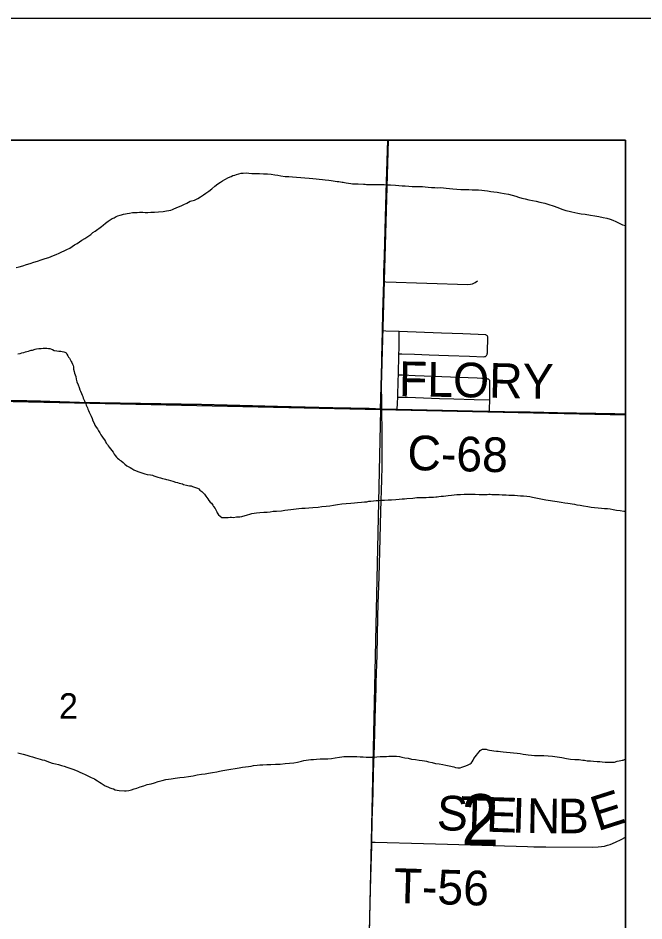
# Model space of a CAD drawing. Extents: x 2.4 to 73.1, y 4.5 to 25.6.
# Drawn here: x 35.8 to 36.312, y 24.146 to 24.885 of the extents above; entities that cross this region are included whole.
import ezdxf

# ---------------------------------------------------------------- set-up
doc = ezdxf.new("R2010")
doc.units = 0
for name, color, linetype in [('GM_X_County_Road', 7, 'Continuous'), ('GM_X_County_Road_Text', 7, 'Continuous'), ('GM_X_Interchange_Ramps', 7, 'Continuous'), ('GM_X_Minor_River', 7, 'Continuous'), ('GM_X_Section', 7, 'Continuous'), ('GM_X_Section_Text', 7, 'Continuous'), ('GM_X_State_Route', 7, 'Continuous'), ('GM_X_Township_Road', 7, 'Continuous'), ('GM_X_Township_Road_Text', 7, 'Continuous'), ('GM_X_US_Shield', 7, 'Continuous'), ('SH_Cut_Line', 7, 'Continuous'), ('SH_Data', 7, 'Continuous')]:
    doc.layers.add(name, color=color, linetype=linetype)

msp = doc.modelspace()

# ---------------------------------------------------------------- linework, layer by layer
at = {"layer": 'GM_X_County_Road'}
for points in [[(36.09775, 24.56499), (36.10949, 24.56462), (36.11043, 24.5646)], [(36.11043, 24.5646), (36.15984, 24.5635), (36.18439, 24.563), (36.18603, 24.56297), (36.2108, 24.56249), (36.2195, 24.56235), (36.24188, 24.56193), (36.28881, 24.56101), (36.29738, 24.56082)]]:
    msp.add_lwpolyline(points, dxfattribs=at)
at = {"layer": 'GM_X_Interchange_Ramps'}
msp.add_lwpolyline([(35.79125, 24.57227), (35.80687, 24.57187), (35.81806, 24.57163), (35.82569, 24.57146), (35.8339, 24.57128), (35.85005, 24.57076), (35.86657, 24.57026), (35.90005, 24.56968), (35.9501, 24.56885), (35.98148, 24.56812), (36.01225, 24.56734), (36.03494, 24.56679), (36.05754, 24.56627), (36.08746, 24.56558), (36.09258, 24.56544), (36.09763, 24.56527), (36.10937, 24.5649), (36.11031, 24.56487), (36.15972, 24.56377), (36.18427, 24.56327), (36.18592, 24.56324), (36.21068, 24.56276), (36.21939, 24.56263), (36.24176, 24.56221), (36.28869, 24.56128), (36.29738, 24.56109), (36.29738, 24.78522), (33.56842, 24.78522)], dxfattribs=at)
at = {"layer": 'GM_X_Minor_River'}
for points in [[(35.97726, 24.7565), (35.9788, 24.75721), (35.98071, 24.75773), (35.98243, 24.75806), (35.98414, 24.7582), (35.9868, 24.75832), (35.9887, 24.75826), (35.99135, 24.75799), (35.99439, 24.75791), (35.99743, 24.75782), (36.00084, 24.75772), (36.00407, 24.75763), (36.0071, 24.75735), (36.01012, 24.75688), (36.01258, 24.75643), (36.01485, 24.75599), (36.01844, 24.7555), (36.02148, 24.75542), (36.02451, 24.75514), (36.02792, 24.75485), (36.03133, 24.75475), (36.03474, 24.75446), (36.03815, 24.75418), (36.04118, 24.7539), (36.04384, 24.75363), (36.04649, 24.75337), (36.04913, 24.75291), (36.0514, 24.75265), (36.05425, 24.75238), (36.05614, 24.75214), (36.05784, 24.7519), (36.05954, 24.75166), (36.06125, 24.75142), (36.06257, 24.75138), (36.06389, 24.75097), (36.06521, 24.75074), (36.06616, 24.75071), (36.06711, 24.75049), (36.06843, 24.75026), (36.07051, 24.75001), (36.07221, 24.74977), (36.07373, 24.74954), (36.07486, 24.74951), (36.076, 24.74948), (36.07714, 24.74944), (36.07828, 24.74941), (36.08283, 24.74909), (36.08416, 24.74905), (36.0853, 24.74902), (36.08681, 24.74897), (36.08776, 24.74895), (36.08871, 24.74892), (36.09004, 24.74888), (36.09156, 24.74884), (36.09327, 24.74879), (36.09536, 24.74892), (36.09745, 24.74886), (36.09953, 24.7488), (36.10181, 24.74873), (36.10485, 24.74865), (36.10883, 24.74834), (36.11167, 24.74807), (36.11432, 24.7478), (36.11698, 24.74773), (36.11982, 24.74745), (36.12266, 24.74737), (36.12532, 24.7473), (36.12741, 24.74724), (36.12911, 24.74719), (36.13101, 24.74713), (36.13328, 24.74688), (36.13556, 24.74681), (36.1384, 24.74654), (36.14106, 24.74646), (36.14352, 24.7462), (36.1458, 24.74633), (36.14827, 24.74626), (36.15054, 24.746), (36.15319, 24.74573), (36.15603, 24.74527), (36.15925, 24.74499), (36.16247, 24.74471), (36.16551, 24.74481), (36.16912, 24.74471), (36.17177, 24.74463), (36.17443, 24.74455), (36.1769, 24.74448), (36.17955, 24.74422), (36.18182, 24.74396), (36.18428, 24.7437), (36.18693, 24.74324), (36.18958, 24.74298), (36.19222, 24.74252), (36.19487, 24.74206), (36.1979, 24.7416), (36.20149, 24.74111), (36.20752, 24.73942), (36.20977, 24.73859), (36.21241, 24.73776), (36.21524, 24.73711), (36.21826, 24.73645)], [(35.79805, 24.68085), (35.80073, 24.68153), (35.8036, 24.6824), (35.80648, 24.68346), (35.80955, 24.68432), (35.81261, 24.68518), (35.81568, 24.68623), (35.81875, 24.68729), (35.82182, 24.68834), (35.82488, 24.6892), (35.82872, 24.69061), (35.83103, 24.69169), (35.83334, 24.69276), (35.83546, 24.69365), (35.83757, 24.69454), (35.83969, 24.69562), (35.84201, 24.69688), (35.84414, 24.69815), (35.84607, 24.69943), (35.84801, 24.7007), (35.84994, 24.70198), (35.85189, 24.70344), (35.85439, 24.7047), (35.85594, 24.7058), (35.85768, 24.70689), (35.85923, 24.70799), (35.86099, 24.70946), (35.86292, 24.71073), (35.86816, 24.71438), (35.86952, 24.71568), (35.87128, 24.71715), (35.87342, 24.71899), (35.87516, 24.72008), (35.8769, 24.72098), (35.87844, 24.72169), (35.87998, 24.7226), (35.88152, 24.72332), (35.88325, 24.72384), (35.88458, 24.72418), (35.88611, 24.72452), (35.88764, 24.72485), (35.88917, 24.72519), (35.89089, 24.72552), (35.89337, 24.72583), (35.89527, 24.72596), (35.89737, 24.72609), (35.89908, 24.72623), (35.90041, 24.7262), (35.90192, 24.72615), (35.90382, 24.7261), (35.9061, 24.72603), (35.90857, 24.72615), (35.91142, 24.72626), (35.91466, 24.72655), (35.91866, 24.72681), (35.92133, 24.72731), (35.92324, 24.72763), (35.92477, 24.72797), (35.92611, 24.7285), (35.92745, 24.72884), (35.92919, 24.72974), (35.93111, 24.73064), (35.93323, 24.73153), (35.93554, 24.7326), (35.93804, 24.73367), (35.94074, 24.73511), (35.94438, 24.73615), (35.94688, 24.73741), (35.94921, 24.73886), (35.95153, 24.74032), (35.95366, 24.74178), (35.95598, 24.74342), (35.95832, 24.74525), (35.96085, 24.74746), (35.96338, 24.74948), (35.9655, 24.75075), (35.96706, 24.75185), (35.96899, 24.75312), (35.97207, 24.75456), (35.97419, 24.75545), (35.97573, 24.75616), (35.97726, 24.7565)], [(36.21826, 24.73645), (36.22128, 24.73579), (36.22411, 24.73514), (36.22713, 24.73448), (36.23128, 24.7336), (36.23467, 24.73255), (36.23824, 24.73131), (36.24181, 24.73007), (36.24519, 24.72864), (36.24839, 24.72759), (36.25122, 24.72694), (36.25348, 24.7265), (36.25575, 24.72605), (36.2582, 24.72541), (36.26104, 24.72495), (36.26425, 24.72448), (36.2686, 24.72378), (36.27219, 24.7233), (36.27559, 24.72263), (36.27899, 24.72196), (36.2822, 24.7213), (36.28484, 24.72046), (36.28709, 24.71964), (36.28953, 24.71862), (36.29215, 24.71721), (36.29496, 24.71599), (36.29738, 24.71527)], [(35.79961, 24.61026), (35.80152, 24.61059), (35.80286, 24.61093), (35.80439, 24.61127), (35.80573, 24.6118), (35.80688, 24.61215), (35.80822, 24.61249), (35.80957, 24.61302), (35.81052, 24.61318), (35.81148, 24.61334), (35.81358, 24.61404), (35.81492, 24.6142), (35.81664, 24.61453), (35.81854, 24.61466), (35.82025, 24.6148), (35.82177, 24.61476), (35.82329, 24.61472), (35.82462, 24.61468), (35.82575, 24.61445), (35.82707, 24.61404), (35.82801, 24.61363), (35.82932, 24.61302), (35.83158, 24.61258), (35.8331, 24.61234), (35.83462, 24.6123), (35.83594, 24.61207), (35.83707, 24.61185), (35.83801, 24.61163), (35.83914, 24.61103), (35.83968, 24.61006), (35.84039, 24.60852), (35.84113, 24.60755), (35.84186, 24.60658), (35.8433, 24.60406), (35.84384, 24.6031), (35.84437, 24.60175), (35.84472, 24.6006), (35.84507, 24.59945), (35.8452, 24.59754), (35.84572, 24.59563), (35.84606, 24.59448), (35.84659, 24.59313), (35.84693, 24.5916), (35.84744, 24.58949), (35.84795, 24.58739), (35.84882, 24.58489), (35.84971, 24.58258), (35.85042, 24.58085), (35.85095, 24.57951), (35.85166, 24.57778), (35.85219, 24.57643), (35.85272, 24.57527), (35.85306, 24.57393), (35.8536, 24.57278)], [(35.8536, 24.57278), (35.85414, 24.57181), (35.85467, 24.57046), (35.85521, 24.56931), (35.85555, 24.56816), (35.85609, 24.567), (35.85663, 24.56603), (35.85698, 24.56488), (35.85752, 24.56373), (35.85805, 24.56238), (35.85876, 24.56084), (35.85966, 24.5591), (35.86036, 24.55718), (35.86107, 24.55526), (35.86197, 24.55352), (35.86268, 24.55179), (35.86377, 24.55024), (35.86468, 24.54869), (35.86558, 24.54715), (35.86667, 24.5454), (35.86757, 24.54386), (35.8683, 24.54269), (35.86939, 24.54114), (35.8705, 24.53978), (35.87122, 24.53843), (35.87194, 24.53707), (35.87285, 24.53591), (35.87358, 24.53494), (35.87431, 24.53378), (35.87651, 24.53105), (35.87761, 24.52969), (35.87851, 24.52814), (35.87924, 24.52698), (35.88034, 24.52562), (35.88126, 24.52464), (35.88219, 24.52385), (35.88312, 24.52325), (35.88405, 24.52247), (35.88572, 24.52109), (35.8872, 24.5199), (35.88887, 24.51853), (35.89037, 24.51772), (35.89149, 24.51712), (35.89298, 24.51632), (35.89466, 24.51532), (35.89635, 24.51451), (35.8986, 24.51349), (35.90105, 24.51266), (35.9035, 24.51202), (35.90557, 24.51139), (35.90822, 24.51113), (35.90972, 24.5107), (35.91104, 24.51028), (35.91255, 24.50986), (35.91424, 24.50924), (35.91631, 24.50861), (35.91801, 24.50818), (35.91951, 24.50776), (35.92046, 24.50754), (35.9214, 24.50732), (35.92272, 24.50691), (35.9246, 24.50647), (35.92649, 24.50585), (35.92856, 24.50522), (35.93025, 24.50479), (35.93176, 24.50436), (35.93308, 24.50395), (35.9344, 24.50372), (35.93534, 24.50331), (35.9376, 24.50268), (35.93873, 24.50245), (35.94006, 24.50222), (35.94157, 24.50199), (35.94251, 24.50158), (35.94589, 24.50054), (35.94684, 24.50032), (35.94776, 24.49953), (35.94869, 24.49855), (35.95017, 24.49737), (35.95128, 24.49639), (35.95239, 24.49522), (35.95367, 24.49366), (35.9544, 24.4925), (35.95531, 24.49133), (35.95603, 24.48998), (35.95714, 24.48881), (35.95825, 24.48782), (35.95916, 24.48627), (35.95988, 24.48511), (35.96116, 24.48356), (35.96206, 24.48182), (35.96261, 24.48085), (35.96296, 24.47989), (35.96405, 24.47834), (35.96516, 24.47717), (35.96665, 24.47617), (35.9695, 24.47628), (35.97197, 24.47621), (35.97349, 24.47636), (35.97463, 24.47632), (35.97615, 24.47628)], [(35.97615, 24.47628), (35.97863, 24.47659), (35.98129, 24.4767), (35.98301, 24.47703), (35.98779, 24.47823), (35.98952, 24.47894), (35.99124, 24.47946), (35.99315, 24.47978), (35.99506, 24.48011), (35.99772, 24.48022), (36.00096, 24.48051), (36.00381, 24.48062), (36.00629, 24.48093), (36.00877, 24.48124), (36.01143, 24.48135), (36.01562, 24.48161), (36.01829, 24.4821), (36.02077, 24.48241), (36.02325, 24.48272), (36.02534, 24.48304), (36.02744, 24.48336), (36.02973, 24.48349), (36.0322, 24.48379), (36.03505, 24.4839), (36.03791, 24.4842), (36.04114, 24.4843), (36.04553, 24.48474), (36.04857, 24.48504), (36.052, 24.48532), (36.05505, 24.4858), (36.0581, 24.48628), (36.06135, 24.48676), (36.06497, 24.48723), (36.06859, 24.48769), (36.07221, 24.48797), (36.07526, 24.48826), (36.07792, 24.48837), (36.08096, 24.48867), (36.08363, 24.48897), (36.08535, 24.48911), (36.08707, 24.48944), (36.08878, 24.48958), (36.09088, 24.4899), (36.09297, 24.49003), (36.09506, 24.49016), (36.09734, 24.49029), (36.10001, 24.4904), (36.10305, 24.4905), (36.10571, 24.49062), (36.10933, 24.49089), (36.112, 24.4912), (36.11428, 24.49132), (36.11618, 24.49146), (36.11808, 24.49159), (36.12303, 24.49202), (36.12475, 24.49216), (36.12647, 24.49249), (36.12855, 24.49243), (36.13065, 24.49256), (36.13407, 24.49265), (36.13635, 24.49278), (36.13825, 24.49291), (36.13996, 24.49286), (36.14187, 24.493), (36.1432, 24.49315), (36.14453, 24.4933), (36.14625, 24.49363), (36.14816, 24.49377), (36.15006, 24.4939), (36.15197, 24.49423), (36.15482, 24.49453), (36.15692, 24.49466), (36.15921, 24.49497), (36.16225, 24.49507), (36.16529, 24.49518), (36.16795, 24.49529), (36.17118, 24.49539), (36.17422, 24.4953), (36.17744, 24.49502), (36.1801, 24.49494), (36.18219, 24.49507), (36.1839, 24.49502), (36.18542, 24.49517), (36.18656, 24.49514), (36.18789, 24.4951), (36.1896, 24.49505), (36.19168, 24.49499), (36.19396, 24.49492), (36.19624, 24.49486), (36.19813, 24.4948), (36.19965, 24.49476), (36.20173, 24.49451), (36.20382, 24.49445), (36.20648, 24.49437), (36.20894, 24.49411), (36.2114, 24.49385), (36.21387, 24.49378), (36.21652, 24.49351), (36.21898, 24.49325), (36.22125, 24.49281), (36.22389, 24.49235)], [(36.22389, 24.49235), (36.22653, 24.4917), (36.22936, 24.49105), (36.2322, 24.49059), (36.24146, 24.48918), (36.24468, 24.48871), (36.2477, 24.48824), (36.25016, 24.48798), (36.25205, 24.48755), (36.25375, 24.48731), (36.25546, 24.48707), (36.25753, 24.48663), (36.26018, 24.48617), (36.26301, 24.48571), (36.26641, 24.48504), (36.26925, 24.48458), (36.27209, 24.48431), (36.27493, 24.48404), (36.27758, 24.48377), (36.28023, 24.4835), (36.28251, 24.48344), (36.28478, 24.48318), (36.28724, 24.48273), (36.29007, 24.48227), (36.29291, 24.482), (36.29593, 24.48134), (36.29738, 24.4813)], [(35.95295, 24.2663), (35.95581, 24.26679), (35.95887, 24.26727), (35.96249, 24.26793), (35.96479, 24.26843), (35.96746, 24.26892), (35.9707, 24.2694), (35.97414, 24.27006), (35.97757, 24.27053), (35.98082, 24.27101), (35.98369, 24.27169), (35.98616, 24.272), (35.98845, 24.27231), (35.99055, 24.27263), (35.99246, 24.27296), (35.99551, 24.27344), (35.99779, 24.27356), (36.00027, 24.27368), (36.0035, 24.27397), (36.00692, 24.27387), (36.01073, 24.27414), (36.01453, 24.27422), (36.01853, 24.27468), (36.02214, 24.27495), (36.02557, 24.27524), (36.02863, 24.27591), (36.03188, 24.27658), (36.03379, 24.27709), (36.03951, 24.27788), (36.04179, 24.278), (36.04427, 24.27831), (36.04712, 24.27842), (36.05017, 24.27852), (36.0534, 24.27862), (36.05644, 24.27891), (36.0595, 24.27939), (36.06312, 24.27986), (36.06503, 24.28019), (36.06655, 24.28033), (36.06864, 24.28046), (36.07054, 24.28041), (36.07244, 24.28035), (36.07472, 24.28029), (36.07738, 24.2804), (36.08003, 24.28013), (36.0825, 24.28006), (36.08478, 24.28), (36.08667, 24.27994), (36.088, 24.2799), (36.08971, 24.27986), (36.09161, 24.27999), (36.09371, 24.28012), (36.09637, 24.28042), (36.09903, 24.28054), (36.1015, 24.28047), (36.10359, 24.2806), (36.10588, 24.28072), (36.10796, 24.28066), (36.10967, 24.28061), (36.11213, 24.28035), (36.11421, 24.27991), (36.11667, 24.27946), (36.11931, 24.279), (36.12214, 24.27835), (36.12536, 24.27788), (36.12819, 24.27742), (36.13084, 24.27715), (36.13273, 24.27691), (36.13443, 24.27648), (36.13594, 24.27605), (36.13896, 24.27559), (36.1416, 24.27475), (36.14462, 24.27428), (36.14765, 24.27382), (36.1501, 24.27337), (36.15143, 24.27314), (36.15293, 24.27271), (36.15671, 24.27185), (36.15821, 24.27142), (36.15992, 24.27118), (36.16181, 24.27113), (36.16335, 24.27165), (36.16488, 24.27218), (36.16661, 24.2727), (36.16853, 24.2736), (36.17007, 24.27431), (36.17104, 24.27504), (36.17165, 24.27617), (36.17244, 24.27729), (36.17324, 24.27878), (36.17424, 24.28028), (36.17522, 24.28158), (36.17601, 24.28251), (36.17739, 24.28418), (36.17818, 24.2853), (36.17915, 24.28584), (36.1803, 24.28638), (36.18201, 24.28652), (36.18315, 24.28629), (36.18446, 24.28588), (36.18598, 24.28564)], [(36.18598, 24.28564), (36.18787, 24.2854), (36.18957, 24.28516), (36.19165, 24.28491), (36.19317, 24.28467), (36.19487, 24.28444), (36.19714, 24.28418), (36.19979, 24.28391), (36.20282, 24.28364), (36.20567, 24.28355), (36.2085, 24.28309), (36.21115, 24.28283), (36.21361, 24.28238), (36.21569, 24.28194), (36.21758, 24.28169), (36.22042, 24.28142), (36.22288, 24.28116), (36.23048, 24.28113), (36.23389, 24.28103), (36.23768, 24.28073), (36.24147, 24.28024), (36.24525, 24.27956), (36.24902, 24.27889), (36.25242, 24.27822), (36.25583, 24.27793), (36.25773, 24.27788), (36.25944, 24.27783), (36.26076, 24.2776), (36.26228, 24.27755), (36.26379, 24.27732), (36.26606, 24.27688), (36.26871, 24.2768), (36.27118, 24.27654), (36.27402, 24.27627), (36.27629, 24.2762), (36.27838, 24.27595), (36.28084, 24.27588), (36.28255, 24.27583), (36.28426, 24.27578), (36.28578, 24.27574), (36.28729, 24.27569), (36.28825, 24.27586), (36.29055, 24.27655), (36.29208, 24.27689), (36.29341, 24.27704), (36.29456, 24.27739), (36.29551, 24.27755), (36.29667, 24.27809), (36.29738, 24.27856)], [(35.79961, 24.28345), (35.80376, 24.28238), (35.80677, 24.28153), (35.80922, 24.2807), (35.81148, 24.28006), (35.81393, 24.27942), (35.816, 24.27879), (35.8177, 24.27836), (35.81939, 24.27774), (35.82127, 24.27731), (35.82334, 24.27649), (35.82541, 24.27586), (35.82767, 24.27503), (35.8305, 24.27438), (35.83276, 24.27375), (35.83521, 24.27311), (35.83747, 24.27247), (35.83972, 24.27165), (35.84217, 24.27082), (35.84462, 24.27017), (35.84668, 24.26936), (35.84875, 24.26854), (35.85043, 24.26754), (35.8523, 24.26672), (35.85474, 24.2657), (35.85624, 24.2649), (35.85793, 24.26409), (35.85961, 24.26328), (35.86092, 24.26267), (35.86224, 24.26206), (35.86354, 24.26127), (35.86485, 24.26047), (35.86634, 24.25947), (35.86783, 24.25848), (35.86951, 24.25748), (35.87119, 24.25648), (35.87325, 24.25566), (35.87494, 24.25485), (35.87644, 24.25424), (35.87776, 24.25382), (35.87926, 24.25321), (35.88096, 24.25278), (35.88247, 24.25255), (35.88702, 24.25223), (35.88835, 24.25238), (35.89045, 24.2527), (35.89255, 24.25321), (35.89485, 24.2539), (35.89696, 24.2546), (35.89965, 24.25547), (35.90271, 24.25634), (35.90559, 24.2574), (35.90884, 24.25806), (35.91152, 24.25893), (35.91459, 24.25999), (35.91785, 24.26084), (35.92071, 24.26152), (35.9251, 24.26216), (35.92853, 24.26263), (35.93235, 24.26309), (35.93578, 24.26356), (35.9394, 24.26403), (35.94303, 24.26468), (35.94647, 24.26534), (35.9499, 24.26582), (35.95295, 24.2663)]]:
    msp.add_lwpolyline(points, dxfattribs=at)
at = {"layer": 'GM_X_Section'}
msp.add_lwpolyline([(35.59489, 24.57543), (36.09659, 24.5645), (36.08619, 24.08472), (35.58661, 24.08517)], close=True, dxfattribs=at)
at = {"layer": 'GM_X_State_Route'}
for points in [[(36.09775, 24.56499), (36.09743, 24.58978), (36.09761, 24.6072), (36.09817, 24.62894), (36.09855, 24.64387), (36.09925, 24.66935), (36.09945, 24.67682), (36.09992, 24.69048), (36.10073, 24.72219), (36.10167, 24.75108), (36.10265, 24.78522)], [(36.09302, 24.33622), (36.0932, 24.34115), (36.09381, 24.36351), (36.09446, 24.3949), (36.09478, 24.40546), (36.09553, 24.42751), (36.09626, 24.4589), (36.09704, 24.48126), (36.09766, 24.50705), (36.09788, 24.51791), (36.0979, 24.52879), (36.0979, 24.54526), (36.09775, 24.56499)], [(36.08756, 24.13638), (36.08792, 24.14947), (36.08875, 24.18146), (36.08944, 24.20739), (36.0895, 24.2103), (36.0899, 24.22776), (36.09059, 24.25074), (36.09101, 24.26751), (36.09163, 24.28948), (36.09189, 24.30014), (36.09246, 24.32096), (36.09302, 24.33622)]]:
    msp.add_lwpolyline(points, dxfattribs=at)
at = {"layer": 'GM_X_Township_Road'}
msp.add_line((36.11127, 24.59277), (36.11173, 24.61033), dxfattribs=at)
for points in [[(36.09925, 24.66935), (36.10103, 24.66929), (36.16829, 24.66708), (36.17027, 24.66727), (36.17206, 24.66761), (36.17313, 24.66796), (36.17417, 24.66852), (36.17598, 24.66995)], [(36.11192, 24.62841), (36.1011, 24.62882), (36.09817, 24.62894)], [(36.11173, 24.61033), (36.11399, 24.61025), (36.12439, 24.60986), (36.13642, 24.60942), (36.15225, 24.60891), (36.16963, 24.60822), (36.18143, 24.60781), (36.18204, 24.60791), (36.18261, 24.6081), (36.183, 24.60834), (36.18334, 24.60861), (36.18362, 24.60897), (36.18385, 24.60937), (36.18402, 24.60979), (36.18415, 24.61025), (36.18427, 24.61093), (36.18435, 24.61182), (36.1845, 24.62363), (36.18446, 24.62414), (36.18437, 24.62455), (36.18423, 24.62485), (36.18383, 24.62529), (36.18333, 24.62559), (36.183, 24.62566), (36.17679, 24.62597), (36.16402, 24.62648), (36.14669, 24.62707), (36.11192, 24.62841)], [(36.11173, 24.61033), (36.11182, 24.61395), (36.11189, 24.62434), (36.11192, 24.62841)], [(36.11086, 24.57481), (36.11117, 24.58882), (36.11127, 24.59277)], [(36.18617, 24.57257), (36.18629, 24.58522), (36.1863, 24.58755), (36.18626, 24.58791), (36.18617, 24.58824), (36.18598, 24.58859), (36.18576, 24.58889), (36.18547, 24.58914), (36.18508, 24.58936), (36.18466, 24.58954), (36.18405, 24.58967), (36.18343, 24.58974), (36.17571, 24.5902), (36.12518, 24.59223), (36.11465, 24.59263), (36.11127, 24.59277)], [(36.11043, 24.5646), (36.11064, 24.56974), (36.11086, 24.57481)], [(36.11086, 24.57481), (36.1131, 24.57475), (36.11866, 24.57459), (36.14495, 24.57369), (36.15673, 24.5733), (36.17346, 24.5728), (36.18617, 24.57257)], [(35.79136, 24.57199), (35.80699, 24.5716), (35.81818, 24.57136), (35.82581, 24.57119), (35.83402, 24.57101), (35.85016, 24.57049), (35.86669, 24.56999), (35.90017, 24.5694), (35.95021, 24.56858), (35.9816, 24.56784), (36.01237, 24.56706), (36.03505, 24.56652), (36.05766, 24.566), (36.08758, 24.56531), (36.0927, 24.56516), (36.09775, 24.56499)], [(36.18603, 24.56297), (36.18606, 24.56479), (36.18617, 24.57257)], [(36.21716, 24.20665), (36.22216, 24.20649), (36.2321, 24.2063), (36.27034, 24.20617), (36.275, 24.20642), (36.27762, 24.2066), (36.28008, 24.20701), (36.28267, 24.20769), (36.28471, 24.20844), (36.28904, 24.21014), (36.29381, 24.21241), (36.29738, 24.21429)], [(36.0895, 24.2103), (36.09235, 24.21022), (36.13175, 24.20917), (36.15163, 24.20863), (36.21716, 24.20665)]]:
    msp.add_lwpolyline(points, dxfattribs=at)
at = {"layer": 'GM_X_US_Shield'}
for points in [[(36.10293, 24.78522), (35.59806, 24.78522), (35.59489, 24.57543), (36.09659, 24.5645)], [(36.29738, 24.56016), (36.29738, 24.78522), (36.10293, 24.78522), (36.09659, 24.5645)], [(36.29738, 24.07317), (36.29738, 24.56016), (36.09659, 24.5645), (36.08619, 24.08472)]]:
    msp.add_lwpolyline(points, close=True, dxfattribs=at)
at = {"layer": 'SH_Cut_Line'}
msp.add_lwpolyline([(36.29738, 20.02567), (36.29738, 24.78522), (29.49738, 24.78522)], dxfattribs=at)
at = {"layer": 'SH_Data'}
msp.add_line((29.39738, 24.88522), (36.39738, 24.88522), dxfattribs=at)
msp.add_lwpolyline([(29.49738, 24.78522), (36.29738, 24.78522), (36.29738, 17.98522), (29.49738, 17.98522)], close=True, dxfattribs=at)

# ---------------------------------------------------------------- texts
at = {"layer": 'GM_X_County_Road_Text'}
for s, rotation, p in [('FLORY', 358.95647, (36.11154, 24.57563)), ('C-68', 358.6375, (36.11842, 24.51511))]:
    msp.add_text(s, height=0.028409, rotation=rotation, dxfattribs=at).set_placement(p)
at = {"layer": 'GM_X_Section_Text'}
for height, p in [(0.02093, (35.83319, 24.31131)), (0.04186, (36.16277, 24.20774))]:
    msp.add_text('2', height=height, rotation=0.00001, dxfattribs=at).set_placement(p)
at = {"layer": 'GM_X_Township_Road_Text'}
for s, height, rotation, p in [('S', 0.02841, 358.14664, (36.14251, 24.22021)), ('T', 0.02841, 358.14403, (36.16167, 24.21959)), ('E', 0.02841, 17.65569, (36.27455, 24.21907)), ('E', 0.02841, 358.13975, (36.1829, 24.2189)), ('I', 0.02841, 358.24267, (36.2042, 24.21821)), ('N', 0.02841, 359.02874, (36.21629, 24.21784)), ('B', 0.02841, 0.46564, (36.24206, 24.21742)), ('T-56', 0.028409, 358.2328, (36.10706, 24.16059))]:
    msp.add_text(s, height=height, rotation=rotation, dxfattribs=at).set_placement(p)

doc.saveas('drawing.dxf')
